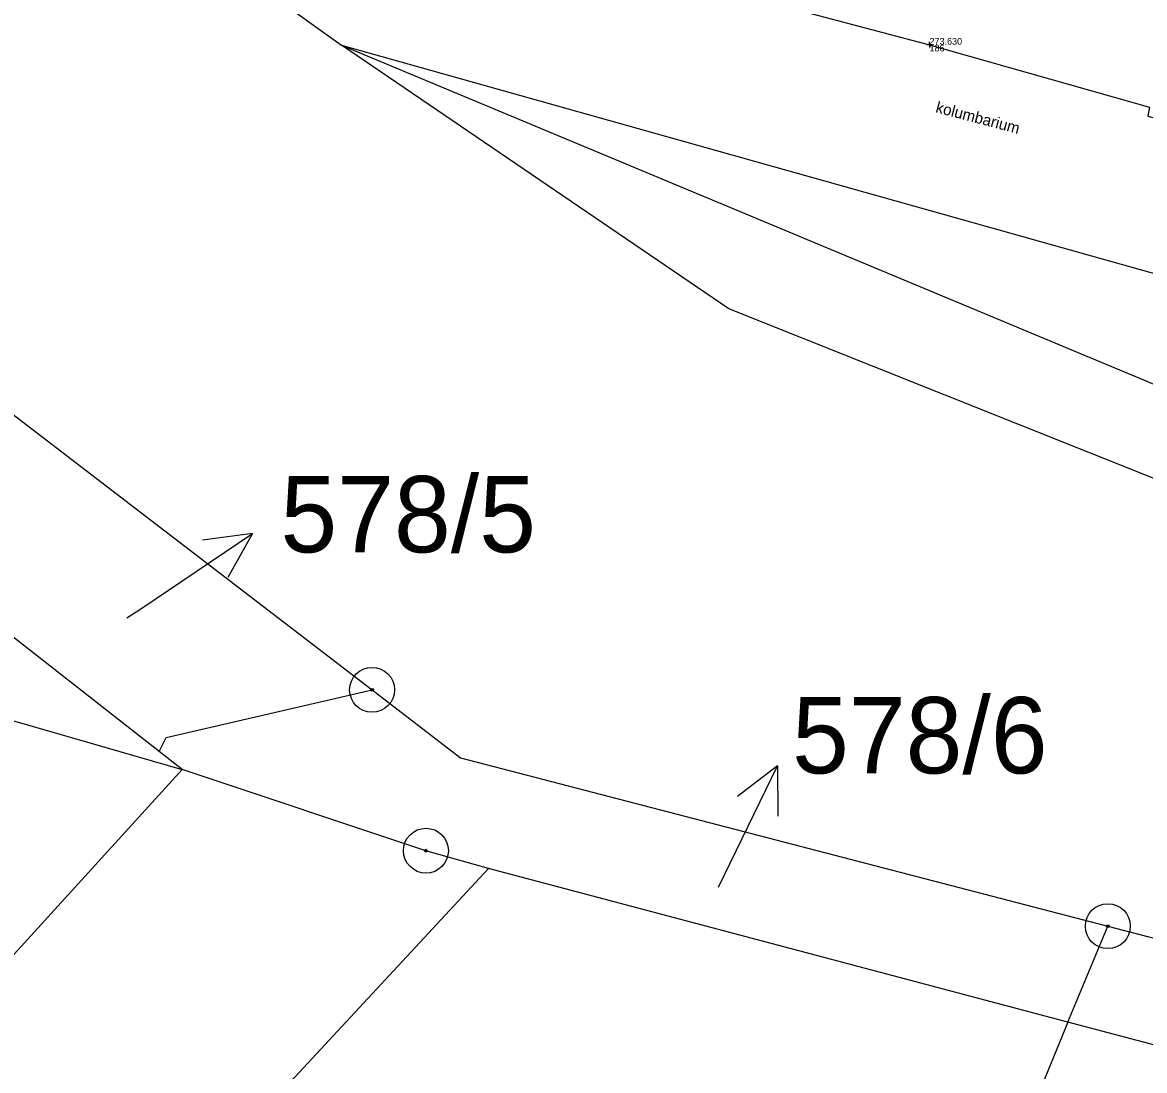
# Model space of a CAD drawing. Extents: x -776606 to -776076, y -974328 to -973875.
# Drawn here: x -776421.12 to -776396.14, y -974220.61 to -974197.28 of the extents above; entities that cross this region are included whole.
import ezdxf

# ---------------------------------------------------------------- set-up
doc = ezdxf.new("R2010")
doc.units = 0
for name, color, linetype in [('Body polohopisu', 7, 'Continuous'), ('Doplňující texty', 7, 'Continuous'), ('Hranice parcel', 7, 'Continuous'), ('Parcelní čísla', 7, 'Continuous'), ('Pop  PČ popisy', 7, 'Continuous'), ('Rozhraní ploch', 7, 'Continuous'), ('Vnitřní kresba', 7, 'Continuous'), ('Výšky bodů', 7, 'Continuous'), ('Značky bodu BP', 7, 'Continuous'), ('Čísla bodů', 7, 'Continuous')]:
    doc.layers.add(name, color=color, linetype=linetype)

msp = doc.modelspace()

# ---------------------------------------------------------------- linework, layer by layer
at = {"layer": 'Body polohopisu'}
for q in [(-776400.993, -974197.78), (-776400.93, -974197.718), (-776400.868, -974197.78), (-776400.93, -974197.843)]:
    msp.add_line((-776400.93, -974197.78), q, dxfattribs=at)
at = {"layer": 'Hranice parcel'}
for p, q in [((-776424.22, -974190.48), (-776414.02, -974197.79)), ((-776405.4, -974203.66), (-776414.02, -974197.79)), ((-776414.02, -974197.79), (-776375.42, -974208.63)), ((-776422.37, -974205.22), (-776413.34, -974212.14)), ((-776418.08, -974213.51), (-776422.47, -974210.08)), ((-776424.09, -974212.03), (-776417.57, -974213.91)), ((-776417.57, -974213.91), (-776418.08, -974213.51)), ((-776417.57, -974213.91), (-776430.93, -974228.6)), ((-776397.85, -974219.54), (-776396.96, -974217.4))]:
    msp.add_line(p, q, dxfattribs=at)
for points in [[(-776372.39, -974215.17), (-776376.43, -974215.22), (-776405.4, -974203.66)], [(-776418.08, -974213.51), (-776417.92, -974213.2), (-776413.34, -974212.14)], [(-776413.34, -974212.14), (-776411.37, -974213.65), (-776396.96, -974217.4)], [(-776397.85, -974219.54), (-776410.75, -974216.12), (-776412.14, -974215.72), (-776417.57, -974213.91)], [(-776396.96, -974217.4), (-776377.08, -974222.57), (-776374.7, -974223.37)], [(-776397.85, -974219.54), (-776399.26, -974222.98), (-776404.25, -974235.1), (-776406.44, -974239.65)], [(-776377.04, -974224.25), (-776384.52, -974222.93), (-776389.85, -974221.65), (-776397.85, -974219.54)]]:
    msp.add_lwpolyline(points, dxfattribs=at)
at = {"layer": 'Pop  PČ popisy'}
for p, q in [((-776418.49, -974210.34), (-776416.002, -974208.662)), ((-776416.002, -974208.662), (-776417.112, -974208.807)), ((-776416.002, -974208.662), (-776416.552, -974209.637)), ((-776418.8, -974210.54), (-776418.49, -974210.34)), ((-776405.63, -974216.53), (-776404.314, -974213.833)), ((-776404.314, -974213.833), (-776405.204, -974214.513)), ((-776404.314, -974213.833), (-776404.303, -974214.952))]:
    msp.add_line(p, q, dxfattribs=at)
at = {"layer": 'Rozhraní ploch'}
msp.add_lwpolyline([(-776402.27, -974182.15), (-776402.11, -974182.26), (-776405.58, -974189.05), (-776409.09, -974195.51), (-776404.69, -974196.79), (-776400.93, -974197.78), (-776396.03, -974199.17), (-776396.07, -974199.37), (-776395.22, -974199.6), (-776395.17, -974199.4), (-776393.77, -974199.81), (-776393.73, -974199.63), (-776391.65, -974200.17), (-776391.69, -974200.35), (-776390.84, -974200.57), (-776390.78, -974200.41), (-776385.82, -974201.79), (-776382.94, -974202.63), (-776383.306, -974203.936)], dxfattribs=at)
at = {"layer": 'Vnitřní kresba'}
for p, q in [((-776414.02, -974197.79), (-776372.39, -974215.17)), ((-776424.97, -974231.42), (-776410.75, -974216.12))]:
    msp.add_line(p, q, dxfattribs=at)
at = {"layer": 'Značky bodu BP'}
for centre, radius in [((-776413.34, -974212.14), 0.5), ((-776413.34, -974212.14), 0.0303), ((-776412.14, -974215.72), 0.5), ((-776412.14, -974215.72), 0.0303), ((-776396.96, -974217.4), 0.5), ((-776396.96, -974217.4), 0.0303)]:
    msp.add_circle(centre, radius, dxfattribs=at)

# ---------------------------------------------------------------- texts
at = {"layer": 'Doplňující texty'}
msp.add_text('kolumbarium', height=0.25, rotation=345.2489, dxfattribs=at).set_placement((-776400.809, -974199.281))
at = {"layer": 'Parcelní čísla'}
for s, p in [('578/5', (-776415.38, -974209.08)), ('578/6', (-776403.99, -974214))]:
    msp.add_text(s, height=1.7, dxfattribs=at).set_placement(p)
at = {"layer": 'Výšky bodů'}
msp.add_text('273.630', height=0.15, dxfattribs=at).set_placement((-776400.93, -974197.78))
at = {"layer": 'Čísla bodů'}
msp.add_text('186', height=0.15, dxfattribs=at).set_placement((-776400.93, -974197.93))

doc.saveas('drawing.dxf')
